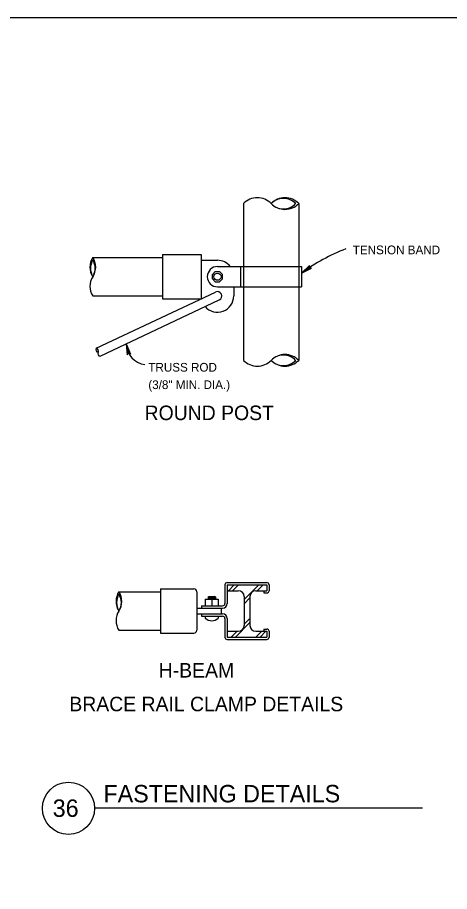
# Model space of a CAD drawing. Extents: x -123486 to -116575, y -107066 to -101122.
# Drawn here: x -119084 to -118786, y -101724 to -101122 of the extents above; entities that cross this region are included whole.
import ezdxf

# ---------------------------------------------------------------- set-up
doc = ezdxf.new("R2010")
doc.units = 0
for name, color, linetype in [('Default', 7, 'Continuous'), ('G-MARK', 7, 'Continuous'), ('Misc CnstDet(22)', 7, 'Continuous')]:
    doc.layers.add(name, color=color, linetype=linetype)

msp = doc.modelspace()

# ---------------------------------------------------------------- linework, layer by layer
at = {"layer": 'Default'}
msp.add_lwpolyline([(-119542.38, -101122.36), (-117742.38, -101122.36), (-117742.38, -102572.36), (-119542.38, -102572.36)], close=True, dxfattribs=at)
at = {"layer": 'G-MARK'}
for p, q in [((-118928.03, -101250.51), (-118928.03, -101293.9)), ((-118890.03, -101250.51), (-118890.03, -101293.9)), ((-119031.94, -101287.62), (-118983.83, -101287.62)), ((-118983.83, -101285.62), (-118983.83, -101316.18)), ((-118983.83, -101285.62), (-118957.27, -101285.62)), ((-118957.27, -101285.62), (-118957.27, -101314.18)), ((-118957.27, -101289.62), (-118946.03, -101289.62)), ((-118946.03, -101293.9), (-118888.03, -101293.9)), ((-118930.03, -101293.9), (-118930.03, -101307.9)), ((-118928.03, -101293.9), (-118928.03, -101307.9)), ((-118890.03, -101293.9), (-118890.03, -101307.9)), ((-118888.03, -101298.36), (-118882.46, -101293.22)), ((-118888.03, -101298.36), (-118882.62, -101293.7)), ((-118888.03, -101293.9), (-118888.03, -101307.9)), ((-118888.03, -101298.36), (-118882.64, -101294.04)), ((-118888.03, -101298.36), (-118882.6, -101294.32)), ((-118888.03, -101298.36), (-118882.48, -101294.56)), ((-118888.03, -101298.36), (-118882.34, -101294.72)), ((-118888.03, -101298.36), (-118882.11, -101294.87)), ((-118888.03, -101298.36), (-118881.79, -101294.98)), ((-118888.03, -101298.36), (-118881.22, -101295.01)), ((-118949.53, -101299.45), (-118947.48, -101297.4)), ((-118949.53, -101302.35), (-118949.53, -101299.45)), ((-118947.48, -101297.4), (-118944.58, -101297.4)), ((-118944.58, -101297.4), (-118942.53, -101299.45)), ((-118942.53, -101302.35), (-118942.53, -101299.45)), ((-118949.53, -101302.35), (-118947.48, -101304.4)), ((-118947.48, -101304.4), (-118944.58, -101304.4)), ((-118944.58, -101304.4), (-118942.53, -101302.35)), ((-119029.51, -101350.24), (-118947.3, -101311.46)), ((-118946.03, -101307.9), (-118888.03, -101307.9)), ((-118934.75, -101307.9), (-118934.75, -101314.18)), ((-118928.03, -101307.9), (-118928.03, -101358.51)), ((-118890.03, -101307.9), (-118890.03, -101358.51)), ((-119031.94, -101314.18), (-118983.83, -101314.18)), ((-119026.95, -101355.67), (-118944.74, -101316.89)), ((-118983.83, -101316.18), (-118957.09, -101316.18)), ((-119008.87, -101347.14), (-119007.33, -101353.5)), ((-119008.87, -101347.14), (-119008.16, -101354.69)), ((-119008.87, -101347.14), (-119006.05, -101354.17)), ((-119008.87, -101347.14), (-119007.93, -101354.17)), ((-119008.87, -101347.14), (-119007.71, -101353.91)), ((-119008.87, -101347.14), (-119007.48, -101353.75)), ((-119008.87, -101347.14), (-119007.02, -101353.65)), ((-119008.87, -101347.14), (-119006.74, -101353.71)), ((-119008.87, -101347.14), (-119006.44, -101353.85)), ((-119008.87, -101347.14), (-119007.28, -101353.67)), ((-118939.23, -101511.56), (-118912.03, -101511.56)), ((-119013.92, -101517.88), (-118985.26, -101517.88)), ((-118985.26, -101515.88), (-118985.26, -101546.44)), ((-118985.26, -101515.88), (-118962.23, -101515.88)), ((-118960.23, -101517.88), (-118960.23, -101544.44)), ((-118940.83, -101513.16), (-118940.83, -101525.96)), ((-118939.23, -101513.16), (-118912.03, -101513.16)), ((-118939.23, -101513.16), (-118939.23, -101525.96)), ((-118939.23, -101517.16), (-118931.63, -101517.16)), ((-118938.41, -101517.16), (-118934.41, -101513.16)), ((-118935.59, -101517.16), (-118931.59, -101513.16)), ((-118927.63, -101523.35), (-118917.44, -101513.16)), ((-118919.63, -101517.16), (-118912.03, -101517.16)), ((-118918.62, -101517.16), (-118914.62, -101513.16)), ((-118913.95, -101517.16), (-118913.95, -101518.76)), ((-118912.03, -101513.16), (-118912.03, -101517.16)), ((-118910.43, -101513.16), (-118910.43, -101517.16)), ((-118954.44, -101523.12), (-118954.44, -101527.56)), ((-118954.44, -101523.12), (-118945.44, -101523.12)), ((-118952.44, -101521.49), (-118952.04, -101521.09)), ((-118952.44, -101521.49), (-118952.44, -101523.12)), ((-118952.44, -101521.49), (-118947.44, -101521.49)), ((-118952.44, -101521.89), (-118947.44, -101521.89)), ((-118952.44, -101522.29), (-118947.44, -101522.29)), ((-118952.44, -101522.69), (-118947.44, -101522.69)), ((-118952.04, -101521.09), (-118947.84, -101521.09)), ((-118952.04, -101521.29), (-118947.84, -101521.29)), ((-118952.04, -101521.69), (-118947.84, -101521.69)), ((-118952.04, -101522.09), (-118947.84, -101522.09)), ((-118952.04, -101522.49), (-118947.84, -101522.49)), ((-118952.04, -101522.89), (-118947.84, -101522.89)), ((-118949.94, -101523.12), (-118949.94, -101527.56)), ((-118947.44, -101521.49), (-118947.84, -101521.09)), ((-118947.44, -101521.49), (-118947.44, -101523.12)), ((-118945.44, -101523.12), (-118945.44, -101527.56)), ((-118927.63, -101521.16), (-118927.63, -101541.16)), ((-118927.63, -101526.18), (-118923.63, -101522.18)), ((-118923.63, -101521.16), (-118923.63, -101541.16)), ((-118913.95, -101518.76), (-118912.03, -101518.76)), ((-118960.23, -101529.16), (-118942.43, -101529.16)), ((-118956.98, -101527.56), (-118942.43, -101527.56)), ((-118956.98, -101527.56), (-118956.98, -101529.16)), ((-118943.57, -101529.16), (-118943.57, -101533.16)), ((-118960.23, -101533.16), (-118942.43, -101533.16)), ((-118956.98, -101533.16), (-118956.98, -101534.76)), ((-118956.98, -101534.76), (-118942.43, -101534.76)), ((-118954.44, -101534.76), (-118954.44, -101536.07)), ((-118945.44, -101534.76), (-118945.44, -101536.07)), ((-118927.63, -101540.32), (-118923.63, -101536.32)), ((-118940.83, -101536.36), (-118940.83, -101549.16)), ((-118939.23, -101536.36), (-118939.23, -101549.16)), ((-118933.65, -101549.16), (-118923.63, -101539.15)), ((-119013.92, -101544.44), (-118985.26, -101544.44)), ((-118985.26, -101546.44), (-118962.23, -101546.44)), ((-118939.23, -101545.16), (-118931.63, -101545.16)), ((-118936.47, -101549.16), (-118932.47, -101545.16)), ((-118919.63, -101545.16), (-118912.03, -101545.16)), ((-118919.5, -101549.16), (-118915.5, -101545.16)), ((-118916.67, -101549.16), (-118912.67, -101545.16)), ((-118913.95, -101543.56), (-118912.03, -101543.56)), ((-118913.95, -101543.56), (-118913.95, -101545.16)), ((-118912.03, -101545.16), (-118912.03, -101549.16)), ((-118910.43, -101545.16), (-118910.43, -101549.16)), ((-118939.23, -101549.16), (-118912.03, -101549.16)), ((-118939.23, -101550.76), (-118912.03, -101550.76))]:
    msp.add_line(p, q, dxfattribs=at)
for points in [[(-118881.22, -101295.01), (-118881.79, -101294.98), (-118882.11, -101294.87), (-118882.34, -101294.72), (-118882.49, -101294.53), (-118882.6, -101294.32), (-118882.64, -101294.04), (-118882.62, -101293.7), (-118882.46, -101293.22)], [(-119008.16, -101354.69), (-119007.93, -101354.17), (-119007.71, -101353.91), (-119007.48, -101353.75), (-119007.25, -101353.67), (-119007.02, -101353.65), (-119006.74, -101353.71), (-119006.44, -101353.85), (-119006.05, -101354.17)]]:
    msp.add_lwpolyline(points, dxfattribs=at)
msp.add_circle((-118946.03, -101300.9), 2.5, dxfattribs=at)
for centre, radius, start, end in [((-118918.53, -101259.79), 13.28, 44.33269, 135.66731), ((-118899.53, -101259.79), 13.28, 44.33269, 135.66731), ((-118900.57, -101258.82), 11.86, 44.48129, 135.51871), ((-118899.53, -101241.23), 13.28, 224.33269, 315.66731), ((-118900.57, -101242.57), 11.6, 223.18016, 316.81984), ((-118811.99, -101402.17), 128.68, 110.72916, 126.2238), ((-119021.92, -101294.26), 12.02, 146.47489, 213.52511), ((-119022.46, -101295.15), 11.09, 148.75144, 211.24856), ((-119041.97, -101294.26), 12.02, 326.47489, 33.52511), ((-119041.03, -101295.15), 10.76, 327.67151, 32.32849), ((-118946.03, -101300.9), 7, 90, 270), ((-118946.03, -101300.9), 11.28, 38.35758, 90), ((-119021.92, -101307.54), 12.02, 146.47489, 213.52511), ((-118946.03, -101314.18), 3, 295.47156, 115.47156), ((-118946.03, -101314.18), 11.24, 180, 189.76811), ((-118946.03, -101314.18), 11.24, 220.73167, 0), ((-118994.32, -101346.95), 14.55, 180.72155, 263.21537), ((-119027.96, -101351.17), 1.81, 149.1165, 261.39146), ((-119029.78, -101352.03), 1.81, 329.1165, 81.39146), ((-119026.69, -101353.88), 1.8, 149.07214, 261.43484), ((-118899.53, -101367.79), 13.28, 44.33269, 135.66731), ((-118900.57, -101366.45), 11.6, 43.18016, 136.81984), ((-118918.53, -101349.23), 13.28, 224.33269, 315.66731), ((-118899.53, -101349.23), 13.28, 224.33269, 315.66731), ((-118900.57, -101350.2), 11.86, 224.48129, 315.51871), ((-118939.23, -101513.16), 1.6, 90, 180), ((-118912.03, -101513.16), 1.6, 0, 90), ((-119003.9, -101524.52), 12.02, 146.47489, 213.52511), ((-119023.94, -101524.52), 12.02, 326.47489, 33.52511), ((-118962.23, -101517.88), 2, 0, 90), ((-118931.63, -101521.16), 4, 0, 90), ((-118919.63, -101521.16), 4, 90, 180), ((-118912.03, -101517.16), 1.6, 270, 0), ((-119004.44, -101525.41), 11.09, 148.75144, 211.24856), ((-119023.01, -101525.41), 10.76, 327.67151, 32.32849), ((-118942.43, -101525.96), 1.6, 270, 0), ((-118942.43, -101525.96), 3.2, 270, 0), ((-119003.9, -101537.8), 12.02, 146.47489, 213.52511), ((-118949.94, -101531.22), 6.61, 227.13447, 312.86553), ((-118942.43, -101536.36), 3.2, 0, 90), ((-118942.43, -101536.36), 1.6, 0, 90), ((-118931.63, -101541.16), 4, 270, 0), ((-118919.63, -101541.16), 4, 180, 270), ((-118962.23, -101544.44), 2, 270, 0), ((-118912.03, -101545.16), 1.6, 0, 90), ((-118939.23, -101549.16), 1.6, 180, 270), ((-118912.03, -101549.16), 1.6, 270, 0)]:
    msp.add_arc(centre, radius, start, end, dxfattribs=at)
at = {"layer": 'Misc CnstDet(22)'}
msp.add_line((-118804.59, -101667.06), (-119030.69, -101667.06), dxfattribs=at)
msp.add_circle((-119048.69, -101667.06), 18, dxfattribs=at)

# ---------------------------------------------------------------- texts
at = {"layer": 'G-MARK'}
for s, height, p in [('TENSION BAND', 6, (-118852.75, -101285.45)), ('TRUSS ROD', 6, (-118993.65, -101366.29)), ('(3/8" MIN. DIA.)', 6, (-118993.65, -101378.29)), ('ROUND POST', 10, (-118996.24, -101399.67)), ('H-BEAM', 10, (-118986.52, -101576.99)), ('BRACE RAIL CLAMP DETAILS', 10, (-119048.12, -101600.22))]:
    msp.add_text(s, height=height, dxfattribs=at).set_placement(p)
at = {"layer": 'Misc CnstDet(22)'}
for s, p in [('FASTENING DETAILS', (-119024.59, -101662.96)), ('36', (-119059.55, -101672.96))]:
    msp.add_text(s, height=12, dxfattribs=at).set_placement(p)

doc.saveas('drawing.dxf')
